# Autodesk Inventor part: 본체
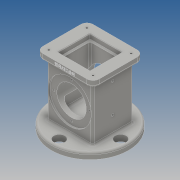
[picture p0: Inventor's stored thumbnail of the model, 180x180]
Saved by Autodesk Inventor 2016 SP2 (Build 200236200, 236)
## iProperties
Created: 2018-10
Part Number: 본체
Material: Generic
Document SubType Name: Modeling
Designer: Administrator
Density: 1 g/cm^3
Appearance: Default
Author: Administrator
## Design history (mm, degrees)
sketch "스케치1"
  geometry: L1 (-46, -41)-(46, -41); L2 (46, -41)-(46, 41); L3 (46, 41)-(-46, 41); L4 (-46, 41)-(-46, -41); L5 (-46, -41)-(46, 41); L6 (46, -41)-(-46, 41); 1 further point
  constraints: 12 end point, 2 midpoint, 2 parallel, 1 horizontal, 1 perpendicular
  dimensions: "d0" = 92 distance of L2.end L3.end; "d1" = 82 distance of L1.end L2.end
extrude "돌출1" new body sketch "스케치1" distance "d2" = 10; taper "d3" = 0 deg
sketch "스케치2"
  geometry: L1 (92, 0)-(0, 0) reference; L2 (0, 0)-(0, -10) reference; 2 further points
  constraints: 1 other
  dimensions: "d4" = 46 distance from line of L2 point (46, -4); "d5" = 4 distance from line of L1 point (46, -4)
feature "엠보싱1" sketch "스케치2" dims "d0" = 92, "d1" = 82, "d6" = 0.5, "d7" = 0, "d8" = 74, "d9" = 66
sketch "스케치3"
  geometry: L1 (-37, -33)-(37, -33); L2 (37, -33)-(37, 33); L3 (37, 33)-(-37, 33); L4 (-37, 33)-(-37, -33); L5 (-37, -33)-(37, 33); L6 (37, -33)-(-37, 33); 1 further point
  constraints: 12 end point, 2 midpoint, 2 parallel, 1 horizontal, 1 perpendicular
  dimensions: "d8" = 74 distance of L2.end L3.end; "d9" = 66 distance of L1.end L2.end
extrude "돌출2" join sketch "스케치3" distance "d10" = 88; taper "d11" = 0 deg
sketch "스케치4"
  geometry: C1 r 62.5 at (0, 0); 1 further point
  constraints: 1 centre point, 1 coincident
  dimensions: "d12" = 125 diameter of C1
extrude "돌출3" join sketch "스케치4" distance "d13" = 10; taper "d14" = 0 deg
sketch "스케치5"
  geometry: C1 r 62.5 at (0, 0) reference; C2 r 9 at (0, 50)
  constraints: 1 centre point, 1 vertical alignment
  dimensions: "d15" = 18 diameter of C2; "d16" = 50 distance of C1.centre C2.centre
extrude "돌출4" cut sketch "스케치5" stored distance "d17" = 10; taper "d18" = 0 deg
fillet "모깎기1" dims "d22" = 3
sketch "스케치7"
  geometry: L1 (26, 26)-(-26, 26); L2 (-26, 26)-(-26, -26); L3 (-26, -26)-(26, -26); L4 (26, -26)-(26, 26); L5 (26, 26)-(-26, -26); L6 (-26, 26)-(26, -26); 1 further point
  constraints: 12 end point, 2 midpoint, 2 parallel, 1 horizontal, 1 perpendicular
  dimensions: "d30" = 52 distance of L2.end L3.end; "d31" = 52 distance of L1.end L2.end
extrude "돌출5" cut sketch "스케치7" distance "d32" = 8; taper "d33" = 0 deg
fillet "모깎기2" dims "d39" = 3
fillet "모깎기3" dims "d40" = 10
sketch "스케치9"
  geometry: A1 r 10 centre (36, -31) between (36, -41) and (46, -31) reference; A2 r 10 centre (36, 31) between (46, 31) and (36, 41) reference; A3 r 10 centre (-36, 31) between (-36, 41) and (-46, 31) reference; A4 r 10 centre (-36, -31) between (-46, -31) and (-36, -41) reference; 5 further points
  constraints: 4 coincident
hole "구멍1" sketch "스케치9" at (36, 31), (-36, 31), (-36, -31), (36, -31) diameter "d41" = 3.242; stored, may be unused: countersink angle "d45" = 90 deg, drill point angle "d47" = 118 deg; dims "d42" = 4, "d43" = 4, "d44" = 2, "d46" = 6
sketch "스케치11"
  geometry: L1 (-22, 22)-(22, 22); L2 (22, 22)-(22, -22); L3 (22, -22)-(-22, -22); L4 (-22, -22)-(-22, 22); L5 (-22, 22)-(22, -22); L6 (22, 22)-(-22, -22); 1 further point
  constraints: 12 end point, 2 midpoint, 2 parallel, 1 horizontal, 1 perpendicular
  dimensions: "d50" = 44 distance of L1.end L2.end; "d51" = 44 distance of L2.end L3.end
extrude "돌출6" cut sketch "스케치11" distance "d52" = 74; taper "d53" = 0 deg
sketch "스케치12"
  geometry: L1 (33, 98)-(33, 10) reference; L2 (33, 54)-(-33, 54); L3 (-33, 10)-(-33, 98) reference; L4 (33, 19)-(30, 19); L5 (30, 19)-(30, 30); L6 (30, 30)-(-30, 30); L7 (-30, 30)-(-30, 19); L8 (-30, 19)-(-33, 19); 1 further point
  constraints: 12 end point, 3 perpendicular, 2 midpoint, 2 point on line
  dimensions: "d54" = 3 distance of L4.start L4.end; "d55" = 3 distance of L7.end L8.end; "d56" = 48 diameter of L6 L2; "d57" = 60 distance of L5.end L6.end; "d58" = 70 diameter of L4 L2; "d59" = 70 diameter of L8 L2
revolve "회전2" sketch "스케치12" stored, may be unused: angle "d60" = 90 deg
sketch "스케치13"
  geometry: C1 r 24 at (0, 0) reference; 2 further points
  constraints: 1 vertical alignment
  dimensions: "d61" = 29 distance of point (0, -29) C1.centre
hole "구멍2" sketch "스케치13" at (0, -29) diameter "d63" = 3.242; stored, may be unused: countersink angle "d67" = 90 deg, drill point angle "d69" = 118 deg; dims "d64" = 4, "d65" = 4, "d66" = 2, "d68" = 6
sketch "스케치14"
  geometry: C1 r 35 at (0, 0) reference; 2 further points
  constraints: 1 vertical alignment
  dimensions: "d73" = 29 distance of point (0, 29) C1.centre
hole "구멍3" sketch "스케치14" at (0, 29) diameter "d74" = 3.242; stored, may be unused: countersink angle "d78" = 90 deg, drill point angle "d80" = 118 deg; dims "d75" = 4, "d76" = 4, "d77" = 2, "d79" = 6
sketch "스케치16"
  geometry: L1 (10, 4)-(10, 56) reference; L2 (-98, 21)-(-98, 39) reference; 4 further points
  constraints: 2 horizontal alignment, 1 coincident, 1 midpoint
  dimensions: "d86" = 48 distance of point (-61, 30) point (-13, 30); "d87" = 37 distance from line of L2 point (-61, 30)
hole "구멍4" sketch "스케치16" at (-13, 30), (-61, 30) diameter "d88" = 4.134; stored, may be unused: countersink angle "d92" = 90 deg, drill point angle "d94" = 118 deg; dims "d89" = 10, "d90" = 4, "d91" = 2, "d93" = 30
fillet "모깎기4" dims "d95" = 3
fillet "모깎기5" dims "d96" = 3
sketch "스케치17"
  geometry: L1 (-9, 108)-(9, 108) reference; L2 (0, 108)-(0, 90); L3 (0, 90)-(28, 90); L4 (28, 90)-(31.174, 108); L5 (62.5, 108)-(-62.5, 108) reference; 1 further point
  constraints: 6 end point, 1 horizontal, 1 midpoint, 1 point on line, 1 vertical
  dimensions: "d98" = 18 distance between parallel lines of L5 L3; "d99" = 80 deg angle of L5 L4; "d100" = 56 diameter of L3.end L2
revolve "회전3" sketch "스케치17" stored, may be unused: angle "d101" = 90 deg
fillet "모깎기6" dims "d102" = 3
fillet "모깎기7" dims "d103" = 3
chamfer "모따기1" distance "d104" = 1; stored, may be unused: second distance "d105" = 2, angle "d106" = 45 deg
node "솔리드1"
pattern_circular "원형 패턴1" dims angle "d20" = 360 deg
pattern_circular "원형 패턴2" dims angle "d71" = 360 deg
pattern_circular "원형 패턴3" dims angle "d82" = 360 deg
